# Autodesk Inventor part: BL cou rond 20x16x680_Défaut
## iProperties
Shininess: 64.0
Length Units: 11269
Angle Units: 11279
Time Units: 11290
Mass Units: 11283
Length Display Precision: 3
Angle Display Precision: 2
Compacted: True
Part Number: BL cou rond 20x16x680_Défaut
Document SubType Name: Modeling
Created: 2006-11
Material: Par défaut
Designer: profs_sti
Density: 0.0
Volumn: 0.0
Area: 0.0
PropertySet Name: Model Information
Control State: 0
Master: False
Checked Out: False
Author: profs_sti
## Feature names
1. Base1
